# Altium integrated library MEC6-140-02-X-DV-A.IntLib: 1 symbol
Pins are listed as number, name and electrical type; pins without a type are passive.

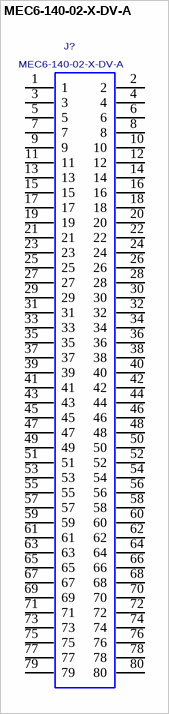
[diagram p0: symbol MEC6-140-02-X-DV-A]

## MEC6-140-02-X-DV-A
designator J?
Mini-Edge-Card Receptacle, 0.635mm Pitch, Vertical Mount, 80 Pins.; MANUFACTURER: SAMTEC
footprint MEC6-140-02-X-DV-A
pins: 1, 2, 3, 4, 5, 6, 7, 8, 9, 10, 11, 12, 13, 14, 15, 16, 17, 18, 19, 20, 21, 22, 23, 24, 25, 26, 27, 28, 29, 30, 31, 32, 33, 34, 35, 36, 37, 38, 39, 40, 41, 42, 43, 44, 45, 46, 47, 48, 49, 50, 51, 52, 53, 54, 55, 56, 57, 58, 59, 60, 61, 62, 63, 64, 65, 66, 67, 68, 69, 70, 71, 72, 73, 74, 75, 76, 77, 78, 79, 80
